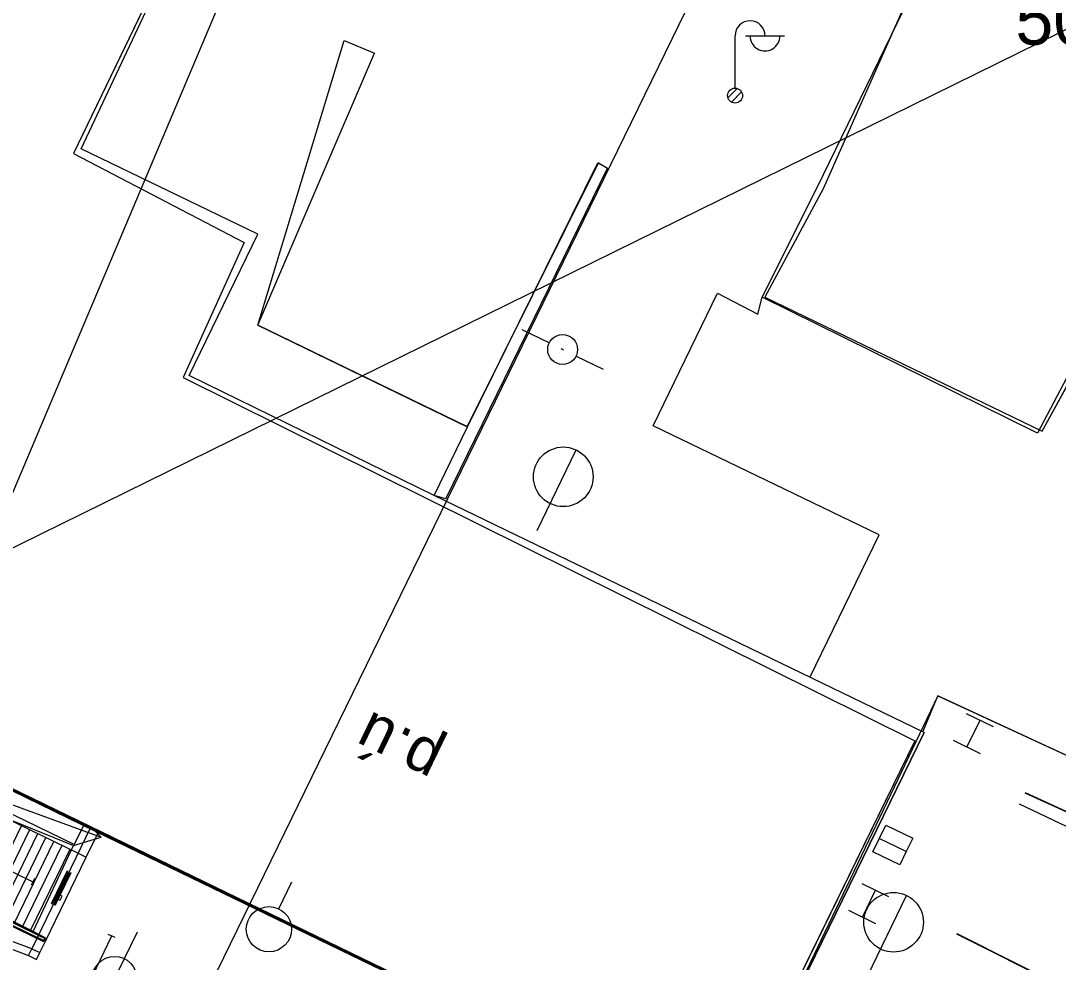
# Model space of a CAD drawing. Extents: x -762314 to -761449, y -993181 to -992589.
# Drawn here: x -761764.9 to -761730.22, y -992888.86 to -992857.4 of the extents above; entities that cross this region are included whole.
import ezdxf

# ---------------------------------------------------------------- set-up
doc = ezdxf.new("R2010")
doc.units = 0
for name, color, linetype in [('Bubliny', 7, 'Continuous'), ('Hranice parcel', 7, 'Continuous'), ('Hranice stavby', 7, 'Continuous'), ('Konstrukce_tenka', 7, 'Continuous'), ('Obvody jako plochy', 7, 'Continuous'), ('Parcelní čísla', 7, 'Continuous'), ('Schodiste_tenka', 7, 'Continuous'), ('SO 2240 hlasové majáčky', 7, 'Continuous'), ('SO 2240 orient syst', 7, 'Continuous'), ('SO 30-61', 7, 'Continuous'), ('SO2020-2023 Zastřešení - demolice', 7, 'Continuous'), ('SO2020-2023_Objekt', 7, 'Continuous'), ('SO_10_20_kresba', 7, 'Continuous'), ('SO_10_20_vyplnění', 7, 'Continuous'), ('Vrstva 11', 7, 'Continuous'), ('Vrstva 12', 7, 'Continuous'), ('Vrstva 13', 7, 'Continuous'), ('Vrstva 14', 7, 'Continuous'), ('Vrstva 16', 7, 'Continuous'), ('Vrstva 17', 7, 'Continuous'), ('Vrstva 23', 7, 'Continuous'), ('Vrstva 25', 7, 'Continuous'), ('Vrstva 36', 7, 'Continuous'), ('Vrstva 41', 7, 'Continuous'), ('Vrstva 43', 7, 'Continuous'), ('Vrstva 47', 7, 'Continuous'), ('Vrstva 51', 7, 'Continuous')]:
    doc.layers.add(name, color=color, linetype=linetype)

msp = doc.modelspace()

# ---------------------------------------------------------------- linework, layer by layer
at = {"layer": 'Bubliny'}
for p, q in [((-761752.079, -992842.201), (-761790.443, -992932.94)), ((-761738.623, -992848.77), (-761773.182, -992919.567)), ((-761725.167, -992855.34), (-761839.481, -992911.581))]:
    msp.add_line(p, q, dxfattribs=at)
at = {"layer": 'Hranice parcel'}
for p, q in [((-761757.285, -992849.706), (-761763.135, -992861.836)), ((-761741.435, -992894.586), (-761827.455, -992852.846)), ((-761735.455, -992857.096), (-761738.085, -992863.016)), ((-761763.135, -992861.836), (-761757.435, -992864.816)), ((-761738.085, -992863.016), (-761740.035, -992866.646)), ((-761757.435, -992864.816), (-761759.475, -992869.326)), ((-761740.035, -992866.646), (-761730.765, -992871.116)), ((-761730.765, -992871.116), (-761728.785, -992867.516)), ((-761759.475, -992869.326), (-761735.015, -992881.466)), ((-761735.015, -992881.466), (-761741.435, -992894.586))]:
    msp.add_line(p, q, dxfattribs=at)
at = {"layer": 'Hranice stavby'}
msp.add_line((-761731.441, -992899.482), (-761829.178, -992852.042), dxfattribs=at)
at = {"layer": 'Konstrukce_tenka'}
msp.add_line((-761771.949, -992884.253), (-761764.312, -992887.961), dxfattribs=at)
for points in [[(-761796.045, -992868.595), (-761777.401, -992877.648), (-761777.205, -992877.243), (-761762.785, -992884.245), (-761763.117, -992884.929), (-761770.34, -992881.421), (-761770.013, -992880.747)], [(-761764.347, -992888.033), (-761772.056, -992884.29), (-761770.689, -992881.474), (-761762.979, -992885.218)], [(-761762.789, -992884.254), (-761762.564, -992884.363), (-761764.53, -992888.411)], [(-761762.979, -992885.218), (-761762.71, -992885.349), (-761762.295, -992884.494), (-761762.564, -992884.363)], [(-761771.472, -992886.041), (-761764.639, -992888.636), (-761764.53, -992888.411), (-761771.385, -992885.861)], [(-761764.312, -992887.961), (-761764.042, -992888.093), (-761764.077, -992888.165), (-761764.347, -992888.033)], [(-761764.53, -992888.411), (-761764.26, -992888.542), (-761764.077, -992888.165)], [(-761764.639, -992888.636), (-761764.369, -992888.767), (-761764.26, -992888.542)]]:
    msp.add_lwpolyline(points, dxfattribs=at)
at = {"layer": 'Obvody jako plochy'}
for p, q in [((-761757.285, -992849.706), (-761763.135, -992861.836)), ((-761741.435, -992894.586), (-761827.455, -992852.846)), ((-761735.455, -992857.096), (-761738.085, -992863.016)), ((-761763.135, -992861.836), (-761757.435, -992864.816)), ((-761738.085, -992863.016), (-761740.035, -992866.646)), ((-761757.435, -992864.816), (-761759.475, -992869.326)), ((-761740.035, -992866.646), (-761730.765, -992871.116)), ((-761730.765, -992871.116), (-761728.785, -992867.516)), ((-761759.475, -992869.326), (-761735.015, -992881.466)), ((-761735.015, -992881.466), (-761741.435, -992894.586))]:
    msp.add_line(p, q, dxfattribs=at)
for points in [[(-761800.165, -992824.186), (-761776.105, -992841.486), (-761776.885, -992844.526), (-761773.725, -992846.066), (-761772.815, -992844.846), (-761768.935, -992846.706), (-761769.205, -992848.226), (-761766.265, -992849.636), (-761764.395, -992847.086), (-761757.285, -992849.706), (-761763.135, -992861.836), (-761757.435, -992864.816), (-761759.475, -992869.326), (-761735.015, -992881.466), (-761741.435, -992894.586), (-761827.455, -992852.846), (-761822.525, -992841.786), (-761791.665, -992856.786), (-761786.825, -992846.566), (-761797.205, -992841.466), (-761800.195, -992847.136), (-761809.025, -992842.736)], [(-761721.985, -992850.566), (-761720.835, -992847.936), (-761719.875, -992846.076), (-761726.955, -992842.646), (-761728.985, -992847.216), (-761730.835, -992846.316), (-761735.455, -992857.096), (-761738.085, -992863.016), (-761740.035, -992866.646), (-761730.765, -992871.116), (-761728.785, -992867.516), (-761721.325, -992850.906)]]:
    msp.add_lwpolyline(points, close=True, dxfattribs=at)
at = {"layer": 'Schodiste_tenka'}
for p, q in [((-761766.201, -992887.044), (-761764.869, -992884.301)), ((-761765.931, -992887.175), (-761764.599, -992884.432)), ((-761765.661, -992887.306), (-761764.329, -992884.563)), ((-761765.391, -992887.437), (-761764.059, -992884.694)), ((-761765.121, -992887.568), (-761763.789, -992884.825)), ((-761764.851, -992887.699), (-761763.519, -992884.956)), ((-761764.582, -992887.83), (-761763.249, -992885.087)), ((-761764.077, -992888.165), (-761762.71, -992885.349))]:
    msp.add_line(p, q, dxfattribs=at)
at = {"layer": 'SO 2240 hlasové majáčky'}
msp.add_lwpolyline([(-761763.583, -992886.787), (-761763.518, -992886.652), (-761763.608, -992886.608), (-761763.673, -992886.743)], close=True, dxfattribs=at)
at = {"layer": 'SO 2240 orient syst'}
for p, q in [((-761763.87, -992886.898), (-761763.346, -992885.818)), ((-761763.749, -992886.956), (-761763.225, -992885.877))]:
    msp.add_line(p, q, dxfattribs=at)
for points in [[(-761763.87, -992886.898), (-761763.852, -992886.907), (-761763.328, -992885.827), (-761763.346, -992885.818)], [(-761763.808, -992886.817), (-761763.371, -992885.917), (-761763.367, -992885.919), (-761763.803, -992886.819)], [(-761763.749, -992886.956), (-761763.767, -992886.948), (-761763.243, -992885.868), (-761763.225, -992885.877)], [(-761763.723, -992886.858), (-761763.287, -992885.958), (-761763.291, -992885.956), (-761763.728, -992886.855)]]:
    msp.add_lwpolyline(points, close=True, dxfattribs=at)
at = {"layer": 'SO 30-61'}
for p, q in [((-761765.85, -992885.52), (-761764.5, -992886.175)), ((-761764.445, -992886.062), (-761764.555, -992886.287)), ((-761761.862, -992887.987), (-761762.517, -992889.337)), ((-761761.749, -992888.042), (-761761.974, -992887.933))]:
    msp.add_line(p, q, dxfattribs=at)
at = {"layer": 'SO2020-2023 Zastřešení - demolice'}
for p, q in [((-761734.252, -992879.962), (-761741.302, -992894.696)), ((-761727.334, -992883.16), (-761734.252, -992879.962))]:
    msp.add_line(p, q, dxfattribs=at)
at = {"layer": 'SO2020-2023_Objekt'}
msp.add_lwpolyline([(-761741.302, -992894.696), (-761777.2, -992877.256), (-761827.829, -992852.697)], dxfattribs=at)
at = {"layer": 'SO_10_20_kresba'}
for p, q in [((-761769.838, -992880.868), (-761762.416, -992884.479)), ((-761762.416, -992884.479), (-761741.302, -992894.696))]:
    msp.add_line(p, q, dxfattribs=at)
at = {"layer": 'SO_10_20_vyplnění'}
msp.add_lwpolyline([(-761709.961, -992919.159), (-761828.894, -992861.43), (-761831.045, -992860.386), (-761831.822, -992860.009), (-761831.285, -992858.902), (-761841.499, -992853.945), (-761838.402, -992847.564), (-761827.829, -992852.697), (-761812.3, -992860.214), (-761802.299, -992865.292), (-761794.461, -992869.272), (-761791.57, -992870.813), (-761786.616, -992873.245), (-761783.335, -992874.861), (-761779.259, -992876.867), (-761777.32, -992877.823), (-761769.838, -992880.868), (-761732.804, -992898.82), (-761732.291, -992897.743), (-761731.948, -992897.855), (-761731.477, -992898.098), (-761733.537, -992902.325), (-761676.025, -992930.201)], dxfattribs=at)
at = {"layer": 'Vrstva 11'}
for p, q in [((-761732.39, -992880.996), (-761733.289, -992880.559)), ((-761733.277, -992881.677), (-761732.839, -992880.777)), ((-761732.827, -992881.895), (-761733.726, -992881.458)), ((-761735.883, -992886.678), (-761736.782, -992886.241)), ((-761736.77, -992887.359), (-761736.332, -992886.459)), ((-761736.32, -992887.577), (-761737.219, -992887.14))]:
    msp.add_line(p, q, dxfattribs=at)
at = {"layer": 'Vrstva 12'}
msp.add_line((-761733.609, -992887.923), (-761733.6, -992887.909), dxfattribs=at)
for points in [[(-761751.087, -992873.263), (-761749.973, -992870.971), (-761756.981, -992867.572)], [(-761756.981, -992867.572), (-761756.979, -992867.572), (-761749.975, -992870.973)], [(-761749.973, -992870.971), (-761749.975, -992870.973)], [(-761719.867, -992894.823), (-761733.609, -992887.923)], [(-761719.871, -992894.818), (-761733.6, -992887.909)]]:
    msp.add_lwpolyline(points, dxfattribs=at)
at = {"layer": 'Vrstva 13'}
for points in [[(-761715.09, -992849.1), (-761715.158, -992849.164), (-761711.463, -992873.127), (-761710.922, -992877.29), (-761712.377, -992881.201), (-761715.123, -992884.492), (-761719.159, -992886.491), (-761723.691, -992886.334), (-761725.656, -992885.799), (-761731.327, -992883.209)], [(-761756.981, -992867.572), (-761754.089, -992858.069)], [(-761754.089, -992858.069), (-761753.08, -992858.487)], [(-761756.979, -992867.572), (-761753.08, -992858.487)], [(-761751.087, -992873.263), (-761749.973, -992870.971), (-761745.613, -992862.151)], [(-761750.696, -992873.384), (-761745.285, -992862.329)], [(-761749.975, -992870.973), (-761745.594, -992862.151)], [(-761745.613, -992862.151), (-761745.285, -992862.329)], [(-761745.613, -992862.151), (-761745.594, -992862.151), (-761745.285, -992862.329)], [(-761750.696, -992873.384), (-761751.087, -992873.263)]]:
    msp.add_lwpolyline(points, dxfattribs=at)
at = {"layer": 'Vrstva 14'}
for points in [[(-761762.415, -992884.479), (-761769.838, -992880.868), (-761769.838, -992880.868), (-761762.416, -992884.479)], [(-761764.078, -992888.048), (-761771.386, -992884.49), (-761770.13, -992881.801), (-761762.212, -992884.687)], [(-761764.137, -992888.17), (-761771.569, -992884.561), (-761771.568, -992884.561), (-761764.137, -992888.17)], [(-761762.212, -992884.687), (-761762.212, -992884.687), (-761762.416, -992884.479), (-761762.415, -992884.479)], [(-761762.415, -992884.479), (-761762.212, -992884.687)], [(-761764.078, -992888.048), (-761764.48, -992887.831), (-761763.131, -992884.968), (-761762.212, -992884.687)], [(-761764.137, -992888.17), (-761764.137, -992888.17), (-761764.078, -992888.048), (-761764.078, -992888.048), (-761764.137, -992888.17)]]:
    msp.add_lwpolyline(points, dxfattribs=at)
at = {"layer": 'Vrstva 16'}
msp.add_lwpolyline([(-761738.518, -992879.33), (-761736.206, -992874.579), (-761743.767, -992870.94), (-761741.61, -992866.504), (-761740.27, -992867.206), (-761740.123, -992866.638)], dxfattribs=at)
at = {"layer": 'Vrstva 17'}
msp.add_lwpolyline([(-761715.09, -992849.1), (-761711.464, -992873.13), (-761710.922, -992877.304), (-761712.378, -992881.208), (-761715.123, -992884.491), (-761719.149, -992886.452), (-761723.692, -992886.337), (-761725.657, -992885.799), (-761731.322, -992883.202)], dxfattribs=at)
at = {"layer": 'Vrstva 23'}
for points in [[(-761738.279, -992862.974), (-761730.219, -992846.397), (-761729.386, -992846.804), (-761727.096, -992842.207), (-761719.73, -992845.828), (-761721.938, -992850.396), (-761721.124, -992850.815), (-761724.291, -992857.518), (-761723.494, -992857.962), (-761725.135, -992861.228), (-761726.336, -992862.492), (-761730.918, -992871.182)], [(-761762.88, -992861.683), (-761758.634, -992852.665), (-761748.285, -992856.444), (-761746.818, -992853.723)], [(-761734.702, -992881.188), (-761751.087, -992873.263), (-761759.267, -992869.256), (-761756.975, -992864.538), (-761762.88, -992861.683)], [(-761730.918, -992871.182), (-761740.123, -992866.638), (-761738.279, -992862.974)], [(-761777.32, -992877.823), (-761769.838, -992880.868), (-761762.416, -992884.479), (-761741.302, -992894.696), (-761734.702, -992881.188), (-761741.302, -992894.696)], [(-761734.743, -992881.141), (-761734.252, -992879.962), (-761727.334, -992883.16), (-761729.076, -992887.03)], [(-761764.48, -992887.831), (-761767.424, -992886.377), (-761768.495, -992885.855), (-761767.291, -992883.196), (-761766.193, -992883.727), (-761763.131, -992884.968)]]:
    msp.add_lwpolyline(points, dxfattribs=at)
at = {"layer": 'Vrstva 25'}
for p, q in [((-761741.025, -992859.655), (-761741.025, -992857.905)), ((-761740.675, -992857.905), (-761739.375, -992857.905)), ((-761741.264, -992859.978), (-761740.953, -992859.667)), ((-761741.144, -992860.123), (-761740.806, -992859.785))]:
    msp.add_line(p, q, dxfattribs=at)
msp.add_circle((-761741.025, -992859.905), 0.25, dxfattribs=at)
msp.add_circle((-761741.025, -992859.905), 0.25, dxfattribs=at)
for centre, start, end in [((-761740.525, -992857.905), 0, 180), ((-761740.025, -992857.911), 179.2974, 0.7026)]:
    msp.add_arc(centre, 0.5, start, end, dxfattribs=at)
at = {"layer": 'Vrstva 36'}
msp.add_line((-761756.273, -992887.08), (-761755.837, -992886.18), dxfattribs=at)
msp.add_circle((-761756.604, -992887.76), 0.757, dxfattribs=at)
at = {"layer": 'Vrstva 41'}
for p, q in [((-761747.238, -992868.17), (-761748.137, -992867.733)), ((-761746.743, -992868.411), (-761746.833, -992868.367)), ((-761746.338, -992868.608), (-761745.439, -992869.045))]:
    msp.add_line(p, q, dxfattribs=at)
msp.add_circle((-761746.788, -992868.389), 0.5, dxfattribs=at)
at = {"layer": 'Vrstva 43'}
for p, q in [((-761747.642, -992874.441), (-761746.331, -992871.747)), ((-761736.603, -992889.325), (-761735.292, -992886.631))]:
    msp.add_line(p, q, dxfattribs=at)
msp.add_lwpolyline([(-761735.304, -992885.165), (-761735.523, -992885.614), (-761736.422, -992885.177), (-761735.985, -992884.278), (-761735.086, -992884.715), (-761735.304, -992885.165), (-761736.204, -992884.727)], dxfattribs=at)
for centre in [(-761746.767, -992872.643), (-761735.728, -992887.527)]:
    msp.add_circle(centre, 0.996, dxfattribs=at)
at = {"layer": 'Vrstva 47'}
msp.add_line((-761762.09, -992890.094), (-761760.996, -992887.846), dxfattribs=at)
msp.add_circle((-761761.762, -992889.42), 0.75, dxfattribs=at)
at = {"layer": 'Vrstva 51'}
msp.add_lwpolyline([(-761725.851, -992886.279), (-761731.517, -992883.583)], dxfattribs=at)

# ---------------------------------------------------------------- texts
at = {"layer": 'Parcelní čísla'}
msp.add_text('505', height=1.7, dxfattribs=at).set_placement((-761731.655, -992858.206))
at = {"layer": 'Vrstva 23'}
msp.add_text('p.ú', height=1.5, rotation=154.1881, dxfattribs=at).set_placement((-761750.706, -992881.664))

doc.saveas('drawing.dxf')
